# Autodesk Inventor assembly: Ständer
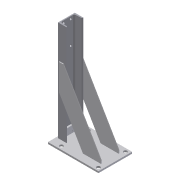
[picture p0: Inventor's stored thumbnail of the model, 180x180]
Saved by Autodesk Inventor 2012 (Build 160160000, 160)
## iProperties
Company: CAD-Verlag
Created: 2004-09
Part Number: Ständer
Document SubType Name: Assembly
Designer: Greiling
Manufacturer: Standard
Standards Organization: Custom
Checked By: Jürgen Kronas
Stock Number: 10-10006
Author: Juergen Kronas
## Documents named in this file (5)
- C:\DemoDaten2012\CAD Daten\Daten Vault 2012 Inventor\Kapitel 4\Anschlag\Ständer.iam
- C:\DemoDaten2012\CAD Daten\Daten Vault 2012 Inventor\Kapitel 4\Anschlag\BreitFlach_Boden.ipt
- C:\DemoDaten2012\CAD Daten\Daten Vault 2012 Inventor\Kapitel 4\Anschlag\Flach_Zyl.ipt
- C:\DemoDaten2012\CAD Daten\Daten Vault 2012 Inventor\Kapitel 4\Anschlag\Blech_Strebe.ipt
- C:\DemoDaten2012\CAD Daten\Daten Vault 2012 Inventor\Kapitel 4\Anschlag\U_100_595.ipt
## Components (5 placed, 4 different names)
1. BreitFlach_Boden:1 — Passend:3, Passend:5, Passend:7, Passend:8, Passend:9, Fluchtend:5
2. Flach_Zyl:1 — Passend:3, Passend:5
3. Blech_Strebe:1 — Passend:7, Fluchtend:3, Fluchtend:4
4. Blech_Strebe:2 — Fluchtend:3, Fluchtend:4
5. DIN 1026  U U 100 - 595:1 — Passend:8, Passend:9, Fluchtend:5
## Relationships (8: Mate 5, Flush 3)
- Passend:3 [Mate]: BreitFlach_Boden:1 ↔ Flach_Zyl:1
- Passend:5 [Mate]: BreitFlach_Boden:1 ↔ Flach_Zyl:1
- Passend:7 [Mate]: BreitFlach_Boden:1 ↔ Blech_Strebe:1
- Fluchtend:3 [Flush]: Blech_Strebe:1 ↔ Blech_Strebe:2
- Fluchtend:4 [Flush]: Blech_Strebe:1 ↔ Blech_Strebe:2
- Passend:8 [Mate]: BreitFlach_Boden:1 ↔ DIN 1026  U U 100 - 595:1
- Passend:9 [Mate]: BreitFlach_Boden:1 ↔ DIN 1026  U U 100 - 595:1
- Fluchtend:5 [Flush]: BreitFlach_Boden:1 ↔ DIN 1026  U U 100 - 595:1
